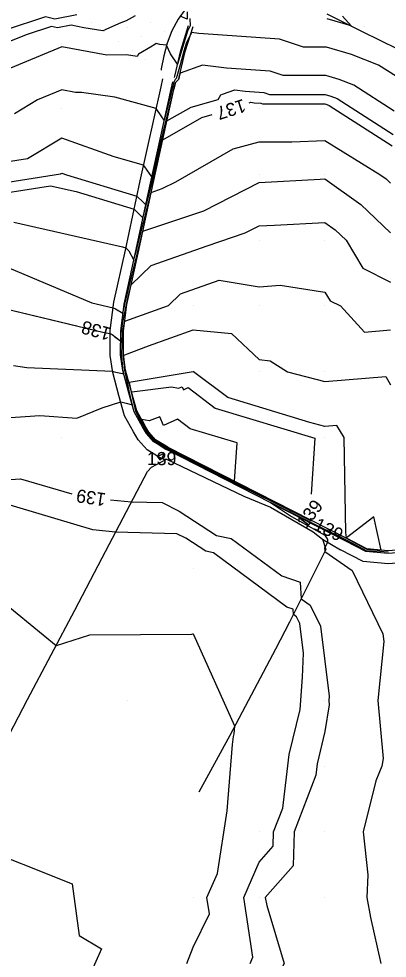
# Model space of a CAD drawing. Extents: x 2354170 to 2357230, y 866100 to 868290.
# Drawn here: x 2354763.4 to 2354819.4, y 867490.8 to 867633.7 of the extents above; entities that cross this region are included whole.
import ezdxf

# ---------------------------------------------------------------- set-up
doc = ezdxf.new("R2010")
doc.units = 0
for name, color, linetype in [('Default', 7, 'Continuous'), ('DTM Contours Minor', 7, 'Continuous'), ('DTM Contours Minor Text', 7, 'Continuous'), ('Exist DTM Drainline', 7, 'Continuous'), ('Exist DTM QL2 LIDAR Elevation Point', 7, 'Continuous'), ('Exist DTM Scan Elevation Point', 7, 'Continuous'), ('Exist Roads Curbs', 7, 'Continuous'), ('Exist Roads EOP', 7, 'Continuous'), ('PH Exist DTM Breakline', 7, 'Continuous')]:
    doc.layers.add(name, color=color, linetype=linetype)

msp = doc.modelspace()

# ---------------------------------------------------------------- linework, layer by layer
at = {"layer": 'Default'}
for points in [[(2354772.25, 867634.31), (2354768.91, 867633.64), (2354767.48, 867634.02), (2354761.39, 867631.99), (2354754.84, 867629.37), (2354753.64, 867628.85), (2354752.76, 867628.87), (2354754.24, 867637.94)], [(2354789.45, 867633.76), (2354789.49, 867632.65), (2354789.11, 867631.82), (2354788.16, 867628.85), (2354788.05, 867628.47), (2354787.59, 867626.79), (2354786.49, 867628.39), (2354785.9, 867629.72), (2354784.89, 867629.8), (2354784.33, 867629.94), (2354784.11, 867629.78), (2354784.01, 867629.74), (2354783.72, 867629.57), (2354781.63, 867628.32), (2354781.44, 867627.97), (2354779.79, 867628.21), (2354776.8, 867628.18), (2354769.97, 867629.42), (2354757.99, 867624.45)], [(2354812.67, 867634.1), (2354813.96, 867632.62), (2354810.32, 867633.71)], [(2354820.84, 867624.92), (2354818.12, 867626.66), (2354814, 867628.26), (2354810.21, 867629.39), (2354806.72, 867629.4), (2354803.07, 867630.61), (2354790.81, 867631.48), (2354789.67, 867631.62), (2354788.88, 867629.93), (2354788.51, 867628.77), (2354787.95, 867626.71), (2354787.46, 867624.91), (2354787.43, 867624.81), (2354787.39, 867624.66), (2354787.19, 867624.46), (2354787.01, 867624.07), (2354786.91, 867623.67), (2354786.74, 867622.99), (2354785.55, 867618.27), (2354785.18, 867618.81), (2354784.32, 867620.05), (2354778.02, 867621.81), (2354772.97, 867622.52), (2354772.06, 867622.52), (2354769.97, 867622.89), (2354766.3, 867621.38), (2354762.81, 867619.27)], [(2354820.53, 867619.65), (2354814.36, 867623.6), (2354812.14, 867624.46), (2354810.1, 867625.07), (2354803.62, 867625.09), (2354801.64, 867625.74), (2354795.02, 867626.21), (2354791.39, 867626.67), (2354787.98, 867625.43), (2354787.84, 867624.94), (2354787.81, 867624.83), (2354787.81, 867624.82), (2354787.72, 867624.49), (2354787.26, 867624.02), (2354787.25, 867624.02), (2354787, 867623.01), (2354786.98, 867622.93), (2354783.65, 867609.67), (2354782.61, 867611.17), (2354782.42, 867611.44), (2354777.94, 867612.69), (2354769.97, 867615.55), (2354764.74, 867612.43), (2354755.35, 867610.95)], [(2354798.45, 867620.92), (2354798.69, 867621.01), (2354799.23, 867620.94), (2354800.22, 867620.87), (2354800.51, 867620.77), (2354809.99, 867620.75), (2354810.28, 867620.66), (2354810.6, 867620.54), (2354820.22, 867614.38)], [(2354757.2, 867606.57), (2354768.26, 867608.31), (2354772.15, 867607.43), (2354780.98, 867604.77), (2354781.71, 867604.05), (2354782.32, 867603.45), (2354783.66, 867608.67), (2354785.33, 867615.31), (2354791.25, 867618.7), (2354792.82, 867619.13)], [(2354762.71, 867602.76), (2354779.23, 867599), (2354779.72, 867598.86), (2354779.76, 867598.82), (2354780.19, 867598.39), (2354780.93, 867596.98), (2354781.13, 867597.81), (2354781.21, 867598.17), (2354783.57, 867607.31), (2354785.25, 867607.88), (2354787.29, 867608.92), (2354796.04, 867613.93), (2354799.97, 867615), (2354804.93, 867614.98), (2354809.97, 867615.21), (2354818.35, 867610.02), (2354819.3, 867609.35), (2354819.97, 867608.7)], [(2354759.97, 867596.64), (2354774.52, 867590.48), (2354777.78, 867589.75), (2354778.13, 867589.58), (2354779.27, 867588.92), (2354779.44, 867589.74), (2354779.55, 867590.3), (2354780.57, 867594.48), (2354781.46, 867598.11), (2354782.3, 867601.39), (2354791.56, 867604.51), (2354799.97, 867608.82), (2354809.26, 867609.31), (2354809.97, 867609.34), (2354815.43, 867605.48), (2354819.97, 867601.13)], [(2354777.98, 867585.39), (2354778.93, 867584.67), (2354778.97, 867585.83), (2354778.98, 867586.2), (2354779.4, 867588.27), (2354779.8, 867590.26), (2354780.01, 867591.15), (2354780.52, 867593.23), (2354783.57, 867596.19), (2354792.07, 867599.19), (2354797.87, 867601.14), (2354799.97, 867602.22), (2354802.29, 867602.34), (2354809.97, 867602.74), (2354811.56, 867601.61), (2354813.22, 867600.02), (2354815.73, 867595.77), (2354819.97, 867593.65)], [(2354762.62, 867580.98), (2354764.66, 867580.68), (2354777.68, 867580.11), (2354777.8, 867580.06), (2354778.19, 867579.97), (2354779.2, 867579.74), (2354779.4, 867579.7), (2354779.3, 867580.2), (2354779.28, 867580.45), (2354779.09, 867582.61), (2354779.16, 867584.21), (2354779.23, 867586.18), (2354779.36, 867586.81), (2354779.54, 867587.7), (2354786.19, 867590.1), (2354788.03, 867591.89), (2354793.91, 867593.96), (2354799.97, 867592.94), (2354803.16, 867593.21), (2354809.97, 867592.14), (2354810.76, 867590.81), (2354812.33, 867590.02), (2354816, 867586.04), (2354819.97, 867586.38)], [(2354759.97, 867589.92), (2354772.26, 867586.98)], [(2354759.97, 867572.91), (2354766.65, 867573.34), (2354772.27, 867572.95), (2354776.13, 867574.55), (2354778.94, 867575.43), (2354779.75, 867575.26), (2354780.7, 867574.99), (2354780.37, 867576.41), (2354780.27, 867576.85), (2354780, 867578.13), (2354779.54, 867580.26), (2354779.35, 867582.55), (2354779.54, 867582.58), (2354783.18, 867583.95), (2354789.97, 867586.41), (2354795.77, 867585.82), (2354799.97, 867581.9), (2354801.63, 867581.68), (2354804.28, 867580.02), (2354809.97, 867578.51), (2354819.22, 867579.27), (2354819.97, 867578.02)], [(2354816.73, 867553.02), (2354818.53, 867552.9), (2354817.39, 867557.97), (2354813.28, 867554.75), (2354813.15, 867555.56), (2354812.92, 867570.02), (2354811.81, 867571.85), (2354809.97, 867571.7), (2354807.67, 867572.31), (2354795.22, 867576.08), (2354789.99, 867580.02), (2354789.98, 867580.03), (2354789.97, 867580.03), (2354789.96, 867580.02), (2354789.95, 867580.02), (2354789.93, 867580.02), (2354780.2, 867578.37), (2354780.51, 867576.92), (2354780.92, 867575.16), (2354781.19, 867574), (2354781.91, 867572.62), (2354782.38, 867571.71), (2354782.54, 867571.4), (2354782.92, 867570.65), (2354783.15, 867570.41), (2354784.04, 867569.43), (2354785.81, 867568.26), (2354785.91, 867568.2), (2354786.33, 867567.99), (2354807.19, 867557.68), (2354807.88, 867557.35)], [(2354789.51, 867571.35), (2354787.55, 867572.82), (2354785.43, 867571.82), (2354784.89, 867573.14), (2354783.25, 867572.55), (2354782.13, 867572.74), (2354782.6, 867571.83), (2354783.03, 867570.99), (2354783.13, 867570.8), (2354784.01, 867569.83), (2354784.2, 867569.63), (2354784.57, 867569.39), (2354786.04, 867568.41), (2354786.2, 867568.33), (2354796.24, 867563.37), (2354796.64, 867569.19), (2354789.51, 867571.35)], [(2354713.62, 867564.77), (2354713.67, 867564.86), (2354714.32, 867566.03), (2354715.08, 867566.39), (2354713.98, 867564.62), (2354714.13, 867556.52), (2354707.39, 867542.85), (2354706.76, 867541.56), (2354719.64, 867552.02), (2354725.37, 867555.42), (2354729.97, 867556.41), (2354733.28, 867556.71), (2354739.97, 867558.09), (2354748.06, 867560.02), (2354749.97, 867560.87), (2354750.58, 867560.62), (2354759.97, 867563.49), (2354763.7, 867563.75), (2354771.49, 867561.44)], [(2354785.18, 867566.81), (2354785.54, 867567.59), (2354784.87, 867567.3), (2354784.48, 867567.19), (2354784.86, 867566.63), (2354785.18, 867566.81)], [(2354777.4, 867560.55), (2354780.59, 867560.23), (2354785.24, 867560.11), (2354787.81, 867558.79), (2354793.5, 867555.12), (2354795.72, 867554.64), (2354803.43, 867548.96), (2354806.21, 867548.03), (2354806.39, 867545.48), (2354807.76, 867544.52), (2354809.31, 867541.32), (2354810.64, 867530.69), (2354810.58, 867530.02), (2354810.63, 867529.35), (2354809.97, 867525.3), (2354808.81, 867520.39), (2354808.59, 867518.64), (2354805.29, 867510.02), (2354805.15, 867504.84), (2354800.88, 867500.02), (2354801.17, 867498.81), (2354803.77, 867490.02), (2354802.47, 867487.52), (2354802.38, 867484.65)], [(2354819.59, 867552.58), (2354818.33, 867552.66), (2354816.25, 867552.8), (2354814.21, 867553.89), (2354813.14, 867554.47), (2354812.97, 867554.55), (2354801.72, 867560.11), (2354804.9, 867557.98), (2354809.98, 867555.16), (2354810.37, 867554.5), (2354810.36, 867554.1), (2354810.04, 867553.31), (2354809.93, 867553.29), (2354809.98, 867552.67), (2354814.12, 867549.78), (2354818.77, 867540.16), (2354818.92, 867538.97), (2354818.03, 867530.02), (2354818.81, 867521.18), (2354818.61, 867520.02), (2354817.74, 867517.79), (2354815.81, 867510.02), (2354816.48, 867503.5), (2354816.35, 867500.02), (2354816.93, 867496.98), (2354818.46, 867490.02)], [(2354813.26, 867554.69), (2354815.93, 867553.25), (2354816.33, 867553.04), (2354816.73, 867553.02)], [(2354788.96, 867490.02), (2354789.97, 867492.48), (2354792.42, 867497.56), (2354792.04, 867500.02), (2354793.63, 867503.68), (2354795.1, 867513.25), (2354795.93, 867523.34), (2354796.08, 867524.51), (2354796.18, 867524.94), (2354796.27, 867526.11), (2354790.07, 867540), (2354790.06, 867540.03), (2354789.97, 867540.12), (2354789.86, 867540.11), (2354789.72, 867540.07), (2354774.19, 867539.93), (2354769.1, 867538.33), (2354761.22, 867544.82)], [(2354714.47, 867520.79), (2354715, 867521.15), (2354716.62, 867524.17), (2354719.31, 867522.66), (2354723.9, 867520.34), (2354731.53, 867516.51), (2354738.06, 867517.13), (2354748.02, 867511.38), (2354749.68, 867510.42), (2354756.25, 867508.21), (2354771.56, 867502.11), (2354772.64, 867494.28), (2354776.03, 867492.25), (2354773.42, 867486.47)]]:
    msp.add_lwpolyline(points, dxfattribs=at)
at = {"layer": 'DTM Contours Minor'}
for points in [[(2354781.13, 867634.17), (2354779.77, 867633.41), (2354778.96, 867633.08), (2354776.79, 867632.13), (2354776.45, 867631.96), (2354776.24, 867631.88), (2354773.33, 867632.34), (2354771.41, 867632.73), (2354769.3, 867632.31), (2354768.39, 867632.55), (2354764.54, 867631.26), (2354754.16, 867627.12), (2354752.27, 867626.3), (2354752.26, 867626.28), (2354752.26, 867626.29), (2354752.26, 867626.3), (2354752.28, 867626.39), (2354754.16, 867637.95)], [(2354789.02, 867634.77), (2354789.06, 867633.67), (2354787.99, 867634.09)], [(2354756.59, 867608.03), (2354769.77, 867610.11), (2354769.97, 867610.22), (2354770.71, 867609.96), (2354781.4, 867606.75), (2354782.36, 867605.8), (2354782.74, 867605.42), (2354783.58, 867608.68), (2354785.96, 867618.18), (2354789.65, 867620.29), (2354793.75, 867621.41), (2354794.13, 867622.15), (2354794.4, 867622.22), (2354796.26, 867622.9), (2354797.83, 867622.7), (2354800.69, 867622.49), (2354801.55, 867622.21), (2354810.02, 867622.19), (2354810.9, 867621.93), (2354811.86, 867621.56), (2354820.33, 867616.13)], [(2354759.97, 867589.92), (2354776.44, 867585.98), (2354777.34, 867585.85), (2354777.61, 867585.67), (2354778.93, 867584.67), (2354778.97, 867585.83), (2354778.98, 867586.2), (2354779.4, 867588.27), (2354779.8, 867590.26), (2354780.01, 867591.15), (2354780.52, 867593.23), (2354783.57, 867596.19), (2354792.07, 867599.19), (2354797.87, 867601.14), (2354799.97, 867602.22), (2354802.29, 867602.34), (2354809.97, 867602.74), (2354811.56, 867601.61), (2354813.22, 867600.02), (2354815.73, 867595.77), (2354819.97, 867593.65)], [(2354780.59, 867576.94), (2354780.59, 867576.95), (2354780.63, 867576.96), (2354786.64, 867577.72), (2354787.74, 867577.54), (2354788.28, 867577.73), (2354788.46, 867577.29), (2354789.17, 867577.62), (2354793.31, 867574.5), (2354808.45, 867569.92), (2354807.87, 867561.4)], [(2354805.67, 867558.53), (2354786.29, 867568.1), (2354785.95, 867568.27), (2354785.4, 867568.64), (2354784.09, 867569.5), (2354783.44, 867570.22), (2354782.99, 867570.7), (2354782.7, 867571.26), (2354782.45, 867571.75), (2354781.7, 867573.19), (2354781.26, 867574.04), (2354781.1, 867574.74), (2354780.59, 867576.94)], [(2354798.59, 867490.02), (2354799.04, 867490.95), (2354797.63, 867500.02), (2354799.97, 867505.42), (2354802.13, 867507.86), (2354802.18, 867510.02), (2354803.56, 867513.61), (2354804.56, 867521.77), (2354806.19, 867528.62), (2354806.58, 867533.54), (2354806.72, 867537.21), (2354806.15, 867541.71), (2354805.64, 867542.76), (2354805.19, 867543.08), (2354805.13, 867543.92), (2354804.21, 867544.23), (2354793.02, 867552.47), (2354791.85, 867552.73), (2354788.82, 867554.68), (2354787.46, 867555.38), (2354778.16, 867555.62), (2354774.67, 867555.97), (2354760.21, 867560.26)]]:
    msp.add_lwpolyline(points, dxfattribs=at)
at = {"layer": 'Exist DTM Drainline'}
msp.add_lwpolyline([(2354787.13, 867624.8), (2354787.17, 867624.98), (2354788.08, 867628.87), (2354789.22, 867632.71)], dxfattribs=at)
at = {"layer": 'Exist DTM QL2 LIDAR Elevation Point'}
for p, q in [((2354769.97, 867630.02), (2354769.97, 867630.02)), ((2354769.97, 867620.02), (2354769.97, 867620.02)), ((2354799.97, 867620.02), (2354799.97, 867620.02)), ((2354809.97, 867620.02), (2354809.97, 867620.02)), ((2354769.97, 867610.02), (2354769.97, 867610.02)), ((2354799.97, 867610.02), (2354799.97, 867610.02)), ((2354809.97, 867610.02), (2354809.97, 867610.02)), ((2354799.97, 867600.02), (2354799.97, 867600.02)), ((2354809.97, 867600.02), (2354809.97, 867600.02)), ((2354789.97, 867590.02), (2354789.97, 867590.02)), ((2354799.97, 867590.02), (2354799.97, 867590.02)), ((2354809.97, 867590.02), (2354809.97, 867590.02)), ((2354789.97, 867580.02), (2354789.97, 867580.02)), ((2354799.97, 867580.02), (2354799.97, 867580.02)), ((2354809.97, 867580.02), (2354809.97, 867580.02)), ((2354769.97, 867570.02), (2354769.97, 867570.02)), ((2354809.97, 867570.02), (2354809.97, 867570.02)), ((2354789.97, 867550.02), (2354789.97, 867550.02)), ((2354789.97, 867540.02), (2354789.97, 867540.02)), ((2354779.97, 867530.02), (2354779.97, 867530.02)), ((2354809.97, 867530.02), (2354809.97, 867530.02)), ((2354809.97, 867520.02), (2354809.97, 867520.02)), ((2354799.97, 867510.02), (2354799.97, 867510.02)), ((2354809.97, 867510.02), (2354809.97, 867510.02)), ((2354789.97, 867500.02), (2354789.97, 867500.02)), ((2354799.97, 867500.02), (2354799.97, 867500.02)), ((2354809.97, 867500.02), (2354809.97, 867500.02))]:
    msp.add_line(p, q, dxfattribs=at)
at = {"layer": 'Exist DTM Scan Elevation Point'}
for p, q in [((2354774.42, 867633.09), (2354774.42, 867633.09)), ((2354779.97, 867632.41), (2354779.97, 867632.41)), ((2354783.43, 867633.12), (2354783.43, 867633.12)), ((2354816.03, 867632.54), (2354816.03, 867632.54)), ((2354776.51, 867631.71), (2354776.51, 867631.71)), ((2354782.06, 867631.03), (2354782.06, 867631.03)), ((2354785.52, 867631.74), (2354785.52, 867631.74)), ((2354818.11, 867631.16), (2354818.11, 867631.16)), ((2354778.59, 867630.33), (2354778.59, 867630.33)), ((2354784.14, 867629.65), (2354784.14, 867629.65)), ((2354780.68, 867628.95), (2354780.68, 867628.95)), ((2354782.76, 867627.57), (2354782.76, 867627.57))]:
    msp.add_line(p, q, dxfattribs=at)
at = {"layer": 'Exist Roads Curbs'}
msp.add_lwpolyline([(2354787.76, 867624.47), (2354787.83, 867624.83), (2354788.74, 867628.72), (2354789.97, 867632.54)], dxfattribs=at)
at = {"layer": 'Exist Roads EOP'}
for points in [[(2354799.11, 867639.65), (2354791.81, 867637.9), (2354790.22, 867636.7), (2354788.81, 867635.28), (2354787.68, 867633.64), (2354786.72, 867631.88), (2354785.98, 867630.02), (2354785.5, 867628.08), (2354785.1, 867626.12), (2354785.06, 867625.89)], [(2354912.39, 867583.62), (2354906.93, 867586.11), (2354901.56, 867588.8), (2354896.21, 867591.51), (2354890.86, 867594.22), (2354885.51, 867596.94), (2354880.16, 867599.65), (2354874.8, 867602.36), (2354869.44, 867605.04), (2354864.06, 867607.71), (2354858.69, 867610.38), (2354853.32, 867613.06), (2354847.95, 867615.73), (2354842.57, 867618.4), (2354837.2, 867621.07), (2354831.83, 867623.74), (2354826.46, 867626.41), (2354821.08, 867629.08), (2354815.71, 867631.75), (2354810.34, 867634.43)]]:
    msp.add_lwpolyline(points, dxfattribs=at)
at = {"layer": 'PH Exist DTM Breakline'}
for p, q in [((2354813.06, 867554.32), (2354785.9, 867568.18)), ((2354786.12, 867568.54), (2354813.25, 867554.69))]:
    msp.add_line(p, q, dxfattribs=at)
for points in [[(2354785.08, 867566.83), (2354782.95, 867568.13), (2354781.57, 867569.67), (2354780.87, 867570.86), (2354779.52, 867573.33), (2354778.66, 867576.41), (2354777.72, 867579.88), (2354777.34, 867582.49), (2354777.34, 867586.3), (2354777.89, 867590.59), (2354779.64, 867598.51), (2354781.89, 867609.05), (2354785.06, 867623.37), (2354785.33, 867624.56)], [(2354785.9, 867568.18), (2354783.97, 867569.36), (2354782.86, 867570.6), (2354782.25, 867571.64), (2354781, 867573.93), (2354780.19, 867576.83), (2354779.27, 867580.2), (2354778.92, 867582.6), (2354778.93, 867586.2), (2354779.45, 867590.32), (2354781.19, 867598.17), (2354783.44, 867608.71), (2354786.6, 867623.02), (2354786.85, 867624.1)], [(2354786.12, 867568.54), (2354784.24, 867569.68), (2354783.19, 867570.85), (2354782.62, 867571.85), (2354781.39, 867574.09), (2354780.59, 867576.94), (2354779.68, 867580.28), (2354779.34, 867582.63), (2354779.34, 867586.18), (2354779.86, 867590.24), (2354781.6, 867598.08), (2354783.85, 867608.63), (2354787.01, 867622.93), (2354787.26, 867624.01)], [(2354861.86, 867585.01), (2354857.69, 867580.24), (2354846.6, 867567.43), (2354838.65, 867558.4), (2354836.27, 867556), (2354833.48, 867553.98), (2354830.22, 867552.53), (2354827.34, 867551.68), (2354823.65, 867551.1), (2354819.57, 867550.8), (2354815.77, 867551.14), (2354812.34, 867552.91)], [(2354860.36, 867585.7), (2354856.49, 867581.28), (2354845.41, 867568.47), (2354837.49, 867559.48), (2354835.24, 867557.21), (2354832.69, 867555.36), (2354829.67, 867554.02), (2354826.99, 867553.23), (2354823.47, 867552.67), (2354819.59, 867552.39), (2354816.22, 867552.69), (2354813.06, 867554.32)], [(2354859.94, 867585.85), (2354856.18, 867581.55), (2354845.09, 867568.75), (2354837.19, 867559.77), (2354834.97, 867557.53), (2354832.48, 867555.72), (2354829.53, 867554.41), (2354826.9, 867553.64), (2354823.42, 867553.09), (2354819.59, 867552.8), (2354816.34, 867553.1), (2354813.25, 867554.69)], [(2354719.97, 867522.44), (2354724.21, 867530.63), (2354756.4, 867514.15), (2354764.74, 867530.18), (2354771.98, 867543.73), (2354776.09, 867551.7), (2354783.03, 867564.85), (2354783.59, 867565.48), (2354785.87, 867566.72)], [(2354785.08, 867566.83), (2354785.87, 867566.72), (2354797.64, 867561.1), (2354801.68, 867559.43), (2354808.21, 867555.65), (2354809.6, 867554.55), (2354812.34, 867552.91)], [(2354809.6, 867554.55), (2354810.14, 867553), (2354804.6, 867541.9), (2354802.46, 867537.83), (2354795.52, 867524.69), (2354790.82, 867516.09)]]:
    msp.add_lwpolyline(points, dxfattribs=at)

# ---------------------------------------------------------------- texts
at = {"layer": 'Default'}
for s, rotation, p in [('137', 197.6446, (2354797.55, 867621.55)), ('138', 164.4665, (2354777.6, 867586.64)), ('139', 171.4547, (2354776.78, 867561.51)), ('139', 333.7139, (2354808.11, 867556.11))]:
    msp.add_text(s, height=2, rotation=rotation, dxfattribs=at).set_placement(p)
msp.add_text('139', height=2, dxfattribs=at).set_placement((2354782.93, 867565.81))
at = {"layer": 'DTM Contours Minor Text'}
msp.add_text('139', height=2, rotation=52.6031, dxfattribs=at).set_placement((2354807.1, 867556.02))

doc.saveas('drawing.dxf')
